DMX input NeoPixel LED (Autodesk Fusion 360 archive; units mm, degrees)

design "DMX input NeoPixel LED" references "3-D NC5FAH", "3D File NC5MAH", "nac3mpxxa", "ELR-02V", "ELR-03V", "5V2AACDC", "xiaodmx"
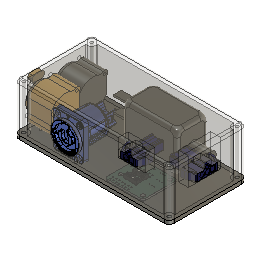
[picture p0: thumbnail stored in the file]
sketch "Sketch1" plane through (0, 0, 0) normal (0, 0, 1) x axis (1, 0, 0)
  line L1 (130, 0) -> (0, 0)
  line L2 (130, 65) -> (130, 0)
  line L3 (0, 65) -> (130, 65)
  line L4 (0, 0) -> (0, 65)
  point P1 (0, 0)
  point P2 (0, 0)
  point P5 (0, 65)
  point P3 (130, 0)
  horizontal L1
  vertical L2
  horizontal L3
  vertical L4
  coincident P1 P2
  dimension "d1" distance P2 P5 = 65
  dimension "d2" distance P2 P3 = 130
component_insert "Component Insert1"
component_insert "Component Insert2"
component_insert "Component Insert3"
component_insert "Component Insert4"
component_insert "Component Insert5"
position "Position1"
extrude "Extrude1" new body sketch "Sketch1" along normal blind 40
fillet "Fillet1" radius 4
shell "Shell1" innerThickness 3
position "Position2"
sketch "Sketch2" plane through (0, 0, 0) normal (0, 0, -1) x axis (1, 0, 0)
  line L1 (126, -3) -> (4, -3)
  line L2 (127, -61) -> (127, -4)
  line L3 (4, -62) -> (126, -62)
  line L4 (3, -4) -> (3, -61)
  line L5 (126, -65) -> (4, -65)
  line L6 (130, -4) -> (130, -61)
  line L7 (4, 0) -> (126, 0)
  line L8 (0, -61) -> (0, -4)
  arc A1 centre (4, -4) radius 1 clockwise from (3, -4) to (4, -3)
  arc A2 centre (126, -4) radius 1 clockwise from (126, -3) to (127, -4)
  arc A3 centre (126, -61) radius 1 clockwise from (127, -61) to (126, -62)
  arc A4 centre (4, -61) radius 1 clockwise from (4, -62) to (3, -61)
  arc A5 centre (4, -61) radius 4 clockwise from (4, -65) to (0, -61)
  arc A6 centre (126, -61) radius 4 clockwise from (130, -61) to (126, -65)
  arc A7 centre (126, -4) radius 4 clockwise from (126, 0) to (130, -4)
  arc A8 centre (4, -4) radius 4 clockwise from (0, -4) to (4, 0)
  circle C1 centre (4, -61) radius 4
  circle C2 centre (4, -4) radius 4
  circle C3 centre (126, -4) radius 4
  circle C4 centre (126, -61) radius 4
  circle C5 centre (4, -4) radius 1.2
  circle C6 centre (126, -4) radius 1.2
  circle C7 centre (126, -61) radius 1.2
  circle C8 centre (4, -61) radius 1.2
  concentric A4 C1
  concentric A1 C2
  concentric A2 C3
  concentric A3 C4
  concentric A1 C5
  concentric A2 C6
  concentric A3 C7
  concentric C1 C8
  dimension "d13" diameter C5 = 2.4
  dimension "d14" diameter C6 = 2.4
  dimension "d15" diameter C7 = 2.4
  dimension "d16" diameter C8 = 2.4
position "Position3"
extrude "Extrude2" add sketch "Sketch2" profile of A1 L1 A2 L2 A3 L3 A4 L4 C1 C2 C3 C4 against normal blind 40
extrude "Extrude3" cut sketch "Sketch2" profile of A1 L1 A2 L2 A3 L3 A4 L4 C5 C6 C7 C8 against normal blind 37
sketch "Sketch3" plane through (0, 0, 0) normal (0, 0, -1) x axis (1, 0, 0)
  line L1 (126, -65) -> (4, -65)
  line L2 (130, -4) -> (130, -61)
  line L3 (4, 0) -> (126, 0)
  line L4 (0, -61) -> (0, -4)
  line L5 (122.127, -3) -> (7.873, -3)
  line L6 (127, -57.127) -> (127, -7.873)
  line L7 (7.873, -62) -> (122.127, -62)
  line L8 (3, -7.873) -> (3, -57.127)
  arc A1 centre (4, -61) radius 4 clockwise from (4, -65) to (0, -61)
  arc A2 centre (126, -61) radius 4 clockwise from (130, -61) to (126, -65)
  arc A3 centre (126, -4) radius 4 clockwise from (126, 0) to (130, -4)
  arc A4 centre (4, -4) radius 4 clockwise from (0, -4) to (4, 0)
  arc A5 centre (126, -4) radius 4 clockwise from (127, -7.873) to (122.127, -3)
  arc A6 centre (126, -61) radius 4 clockwise from (122.127, -62) to (127, -57.127)
  arc A7 centre (4, -61) radius 4 clockwise from (3, -57.127) to (7.873, -62)
  arc A8 centre (4, -4) radius 4 clockwise from (7.873, -3) to (3, -7.873)
  circle C1 centre (4, -61) radius 1.2
  circle C2 centre (4, -4) radius 1.2
  circle C3 centre (126, -61) radius 1.2
  circle C4 centre (126, -4) radius 1.2
extrude "Extrude4" new body sketch "Sketch3" along normal blind 3
sketch "Sketch4" plane through (0, 0, 1.56) normal (0, 0, 1) x axis (-1, 0, 0)
  line L1 (-74.3328, -3.6506) -> (-74.1899, -3.6531)
  line L2 (-102.3114, -3.6506) -> (-74.3328, -3.6506)
  line L3 (-102.4543, -3.6531) -> (-102.3114, -3.6506)
  line L4 (-104.3114, -5.6506) -> (-104.3089, -5.5077)
  line L5 (-104.3114, -30.6828) -> (-104.3114, -5.6506)
  line L6 (-104.3089, -30.8257) -> (-104.3114, -30.6828)
  line L7 (-102.3114, -32.6828) -> (-102.4543, -32.6803)
  line L8 (-74.3328, -32.6828) -> (-102.3114, -32.6828)
  line L9 (-74.1899, -32.6803) -> (-74.3328, -32.6828)
  line L10 (-72.3328, -30.6828) -> (-72.3353, -30.8257)
  line L11 (-72.3328, -5.6506) -> (-72.3328, -30.6828)
  line L12 (-72.3353, -5.5077) -> (-72.3328, -5.6506)
  arc A1 centre (-74.3328, -5.6506) radius 2.0026 clockwise from (-74.1899, -3.6531) to (-72.3353, -5.5077)
  arc A2 centre (-102.3114, -5.6506) radius 2.0026 clockwise from (-104.3089, -5.5077) to (-102.4543, -3.6531)
  arc A3 centre (-102.3114, -30.6828) radius 2.0026 clockwise from (-102.4543, -32.6803) to (-104.3089, -30.8257)
  arc A4 centre (-74.3328, -30.6828) radius 2.0026 clockwise from (-72.3353, -30.8257) to (-74.1899, -32.6803)
  circle C1 centre (-101.238, -6.724) radius 1.5875
  circle C2 centre (-101.238, -29.584) radius 1.5875
  circle C3 centre (-99.65, -17.942) radius 0.3374
  circle C4 centre (-99.65, -24.25) radius 0.3374
  circle C5 centre (-97.65, -17.942) radius 0.3374
  circle C6 centre (-97.65, -24.25) radius 0.3374
  circle C7 centre (-96.094, -30.6) radius 0.3374
  circle C8 centre (-95.65, -17.942) radius 0.3374
  circle C9 centre (-95.65, -24.25) radius 0.3374
  circle C10 centre (-94.094, -30.6) radius 0.3374
  circle C11 centre (-92.094, -30.6) radius 0.3374
  circle C12 centre (-90.57, -5.2) radius 0.4874
  circle C13 centre (-90.57, -7.74) radius 0.4874
  circle C14 centre (-90.57, -22.98) radius 0.4874
  circle C15 centre (-90.57, -25.52) radius 0.4874
  circle C16 centre (-90.58, -11.56) radius 0.3874
  circle C17 centre (-90.58, -19.18) radius 0.3874
  circle C18 centre (-88.03, -5.2) radius 0.4874
  circle C19 centre (-88.03, -7.74) radius 0.4874
  circle C20 centre (-88.03, -22.98) radius 0.4874
  circle C21 centre (-88.03, -25.52) radius 0.4874
  circle C22 centre (-88.04, -11.56) radius 0.3874
  circle C23 centre (-88.04, -19.18) radius 0.3874
  circle C24 centre (-87.268, -30.6) radius 0.4874
  circle C25 centre (-85.49, -5.2) radius 0.4874
  circle C26 centre (-85.49, -7.74) radius 0.4874
  circle C27 centre (-85.49, -22.98) radius 0.4874
  circle C28 centre (-85.49, -25.52) radius 0.4874
  circle C29 centre (-85.5, -11.56) radius 0.3874
  circle C30 centre (-85.5, -19.18) radius 0.3874
  circle C31 centre (-84.728, -30.6) radius 0.4874
  circle C32 centre (-82.95, -5.2) radius 0.4874
  circle C33 centre (-82.95, -7.74) radius 0.4874
  circle C34 centre (-82.95, -22.98) radius 0.4874
  circle C35 centre (-82.95, -25.52) radius 0.4874
  circle C36 centre (-82.96, -11.56) radius 0.3874
  circle C37 centre (-82.96, -19.18) radius 0.3874
  circle C38 centre (-80.434, -28.06) radius 0.4874
  circle C39 centre (-80.434, -30.6) radius 0.4874
  circle C40 centre (-80.41, -5.2) radius 0.4874
  circle C41 centre (-80.41, -7.74) radius 0.4874
  circle C42 centre (-80.41, -22.98) radius 0.4874
  circle C43 centre (-80.41, -25.52) radius 0.4874
  circle C44 centre (-77.894, -28.06) radius 0.4874
  circle C45 centre (-77.894, -30.6) radius 0.4874
  circle C46 centre (-77.87, -5.2) radius 0.4874
  circle C47 centre (-77.87, -7.74) radius 0.4874
  circle C48 centre (-77.87, -22.98) radius 0.4874
  circle C49 centre (-77.87, -25.52) radius 0.4874
  circle C50 centre (-76.6, -12.82) radius 1.5875
  circle C51 centre (-75.354, -28.06) radius 0.4874
  circle C52 centre (-75.354, -30.6) radius 0.4874
  circle C53 centre (-75.33, -5.2) radius 0.4874
  circle C54 centre (-75.33, -7.74) radius 0.4874
  circle C55 centre (-75.33, -22.98) radius 0.4874
  circle C56 centre (-75.33, -25.52) radius 0.4874
extrude "Extrude5" cut sketch "Sketch4" profile of C1 C2 C50 against normal blind 20
sketch "Sketch5" plane through (0, 0, 0) normal (0, 0, 1) x axis (-1, 0, 0)
  line L1 (0, -4) -> (0, -61)
  line L2 (-126, 0) -> (-4, 0)
  line L3 (-130, -61) -> (-130, -4)
  line L4 (-4, -65) -> (-126, -65)
  arc A1 centre (-4, -4) radius 4 clockwise from (-4, 0) to (0, -4)
  arc A2 centre (-126, -4) radius 4 clockwise from (-130, -4) to (-126, 0)
  arc A3 centre (-126, -61) radius 4 clockwise from (-126, -65) to (-130, -61)
  arc A4 centre (-4, -61) radius 4 clockwise from (0, -61) to (-4, -65)
  circle C1 centre (-4, -61) radius 1.2
  circle C2 centre (-126, -61) radius 1.2
  circle C3 centre (-126, -4) radius 1.2
  circle C4 centre (-4, -4) radius 1.2
  circle C5 centre (-101.238, -6.724) radius 1.5875
  circle C6 centre (-76.6, -12.82) radius 1.5875
  circle C7 centre (-101.238, -29.584) radius 1.5875
  circle C8 centre (-4, -4) radius 1.5
  circle C9 centre (-4, -61) radius 1.5
  circle C10 centre (-126, -61) radius 1.5
  circle C11 centre (-126, -4) radius 1.5
  concentric A1 C8
  concentric A4 C9
  concentric A3 C10
  concentric A2 C11
  dimension "d23" diameter C8 = 3
  dimension "d24" diameter C9 = 3
  dimension "d25" diameter C10 = 3
  dimension "d26" diameter C11 = 3
extrude "Extrude6" cut sketch "Sketch5" profile of C1 C2 C3 C4 C8 C9 C10 C11 against normal blind 10
sketch "Sketch6" plane through (0, 0, 0) normal (-1, 0, 0) x axis (0, -1, 0)
  line L1 (-61, 0) -> (-61, 40)
  line L2 (-4, 0) -> (-61, 0)
  line L3 (-4, 40) -> (-4, 0)
  line L4 (-61, 40) -> (-4, 40)
step "GeometricRelationship4" Offset 0
step "GeometricRelationship5" Offset 0
position "Position4"
sketch "Sketch8" plane through (0, 0, 0) normal (-1, 0, 0) x axis (0, -1, 0)
  line L1 (-61, 0) -> (-61, 40)
  line L2 (-4, 0) -> (-61, 0)
  line L3 (-4, 40) -> (-4, 0)
  line L4 (-61, 40) -> (-4, 40)
  line L5 (-4, 0) -> (-61, 40)
  line L6 (-61, 0) -> (-4, 40)
  line L7 (-4, 17) -> (-61, 17)
  line L8 (-32.5, 0) -> (-32.5, 40)
  line L9 (-4, 17) -> (-32.5, 17)
  arc A1 centre (-20.6497, 16.4734) radius 11 clockwise from (-18.1497, 27.1856) to (-23.1497, 27.1856)
  arc A2 centre (-44.2658, 16.4734) radius 8.25 clockwise from (-37.7957, 21.592) to (-39.1472, 22.9435)
  circle C1 centre (-20.5, 17) radius 11
  circle C2 centre (-44.5, 17) radius 11
  circle C3 centre (-30.4, 26.9) radius 1.5
  circle C4 centre (-10.6, 7.1) radius 1.5
  circle C5 centre (-34.6, 7.1) radius 1.5
  circle C6 centre (-54.4, 26.9) radius 1.5
  point P2 (-61, 40)
  point P12 (-61, 40)
  point P4 (-4, 0)
  point P13 (-4, 0)
  point P5 (-4, 40)
  point P14 (-4, 40)
  point P3 (-61, 0)
  point P15 (-61, 0)
  point P16 (-61, 17)
  point P17 (-4, 17)
  point P18 (-32.5, 20)
  point P19 (-32.5, 40)
  point P20 (-32.5, 0)
  point P21 (-32.5, 17)
  point P22 (-32.5, 17)
  point P23 (-20.5, 17)
  point P24 (-44.5, 17)
  point P25 (-30.4, 26.9)
  point P26 (-10.6, 7.1)
  point P27 (-34.6, 7.1)
  point P28 (-54.4, 26.9)
  coincident P2 P12
  coincident P4 P13
  coincident P5 P14
  coincident P3 P15
  coincident L1 P16
  coincident L3 P17
  perpendicular L3 L7
  midpoint L6 P18
  midpoint L4 P19
  midpoint L2 P20
  midpoint L7 P21
  coincident P21 P22
  coincident L9 P23
  coincident L7 P24
  dimension "d79" distance L7 P18 = 3
  dimension "d80" diameter C1 = 22
  dimension "d81" diameter C2 = 22
  dimension "d82" distance P23 P24 = 24
  dimension "d83" distance P21 P23 = 12
  dimension "d84" diameter C3 = 3
  dimension "d85" distance P23 P25 = 9.9
  dimension "d86" distance L9 P25 = 9.9
  dimension "d87" diameter C4 = 3
  dimension "d88" distance P23 P26 = 9.9
  dimension "d89" distance L9 P26 = 9.9
  dimension "d90" diameter C5 = 3
  dimension "d91" distance L7 P27 = 9.9
  dimension "d92" distance P24 P27 = 9.9
  dimension "d93" diameter C6 = 3
  dimension "d94" distance P24 P28 = 9.9
  dimension "d95" distance L7 P28 = 9.9
extrude "Extrude7" cut sketch "Sketch8" profile of C1 C2 C3 C4 C5 C6 against normal blind 9.68
sketch "Sketch9" plane through (0, 0, 0) normal (0, -1, 0) x axis (1, 0, 0)
  line L1 (126, 40) -> (126, 0)
  line L2 (4, 40) -> (126, 40)
  line L3 (4, 0) -> (4, 40)
  line L4 (126, 0) -> (4, 0)
  line L5 (126, 0) -> (4, 40)
  line L6 (4, 0) -> (126, 40)
  line L7 (4, 20) -> (126, 20)
  line L8 (4, 17) -> (126, 17)
  line L9 (65, 0) -> (65, 40)
  line L10 (65, 10.3719) -> (4, 10.3719)
  line L11 (34.5, 40) -> (34.5, 10.3719)
  line L12 (65, 14.0399) -> (34.5, 14.0399)
  line L13 (49.75, 40) -> (49.75, 14.0399)
  line L14 (65, 17) -> (126, 17)
  line L15 (95.5, 40) -> (95.5, 17)
  line L16 (84.25, 34.5) -> (106.75, 34.5)
  line L17 (84.25, 22.5) -> (84.25, 34.5)
  line L18 (106.75, 22.5) -> (84.25, 22.5)
  line L19 (106.75, 34.5) -> (106.75, 22.5)
  line L20 (84.25, 22.5) -> (106.75, 34.5)
  line L21 (106.75, 22.5) -> (84.25, 34.5)
  line L22 (84.25, 40) -> (84.25, 34.5)
  line L23 (106.75, 40) -> (106.75, 34.5)
  line L24 (87.25, 31.5) -> (103.75, 31.5)
  line L25 (87.25, 25.5) -> (87.25, 31.5)
  line L26 (103.75, 25.5) -> (87.25, 25.5)
  line L27 (103.75, 31.5) -> (103.75, 25.5)
  line L28 (87.25, 25.5) -> (103.75, 31.5)
  line L29 (103.75, 25.5) -> (87.25, 31.5)
  line L30 (92.9, 36.5) -> (98.1, 36.5)
  line L31 (92.9, 31.5) -> (92.9, 36.5)
  line L32 (98.1, 31.5) -> (92.9, 31.5)
  line L33 (98.1, 36.5) -> (98.1, 31.5)
  line L34 (92.9, 31.5) -> (98.1, 36.5)
  line L35 (98.1, 31.5) -> (92.9, 36.5)
  line L36 (88, 31.5) -> (103, 31.5)
  line L37 (88, 25.5) -> (88, 31.5)
  line L38 (103, 25.5) -> (88, 25.5)
  line L39 (103, 31.5) -> (103, 25.5)
  line L40 (88, 25.5) -> (103, 31.5)
  line L41 (103, 25.5) -> (88, 31.5)
  line L42 (92.9, 31.5) -> (98.1, 31.5)
  line L43 (92.9, 32.35) -> (92.9, 31.5)
  line L44 (98.1, 32.35) -> (92.9, 32.35)
  line L45 (98.1, 31.5) -> (98.1, 32.35)
  line L46 (92.9, 32.35) -> (98.1, 31.5)
  line L47 (98.1, 32.35) -> (92.9, 31.5)
  line L48 (49.75, 15.3146) -> (34.5, 15.3146)
  line L49 (42.125, 40) -> (42.125, 15.3146)
  circle C1 centre (42.125, 17) radius 12
  circle C2 centre (32.625, 29) radius 1.5
  circle C3 centre (51.625, 5) radius 1.5
  point P4 (4, 40)
  point P6 (4, 40)
  point P2 (126, 0)
  point P7 (126, 0)
  point P3 (126, 40)
  point P8 (126, 40)
  point P5 (4, 0)
  point P9 (4, 0)
  point P10 (126, 20)
  point P11 (4, 20)
  point P12 (126, 17)
  point P13 (4, 17)
  point P14 (65, 40)
  point P15 (65, 0)
  point P16 (4, 10.3719)
  point P17 (65, 10.3719)
  point P18 (34.5, 10.3719)
  point P19 (34.5, 40)
  point P20 (34.5, 14.0399)
  point P21 (65, 14.0399)
  point P22 (49.75, 14.0399)
  point P23 (49.75, 40)
  point P25 (65, 17)
  point P26 (95.5, 17)
  point P27 (95.5, 40)
  point P28 (95.5, 28.5)
  point P33 (95.5, 28.5)
  point P34 (84.25, 40)
  point P35 (106.75, 40)
  point P40 (95.5, 28.5)
  point P45 (95.5, 34)
  point P43 (92.9, 31.5)
  point P50 (95.5, 28.5)
  point P55 (95.5, 31.925)
  point P52 (92.9, 31.5)
  point P56 (32.625, 29)
  point P57 (32.625, 29)
  point P58 (51.625, 5)
  point P59 (51.625, 5)
  point P60 (34.5, 15.3146)
  point P61 (49.75, 15.3146)
  point P62 (42.125, 15.3146)
  point P63 (42.125, 40)
  point P64 (42.125, 17)
  point P31 (84.25, 22.5)
  point P32 (106.75, 22.5)
  point P30 (84.25, 34.5)
  point P38 (87.25, 25.5)
  point P39 (103.75, 25.5)
  point P37 (87.25, 31.5)
  point P44 (98.1, 31.5)
  point P42 (92.9, 36.5)
  point P48 (88, 25.5)
  point P49 (103, 25.5)
  point P47 (88, 31.5)
  point P53 (92.9, 32.35)
  coincident P4 P6
  coincident P2 P7
  coincident P3 P8
  coincident P5 P9
  midpoint L1 P10
  midpoint L3 P11
  coincident L1 P12
  coincident L3 P13
  perpendicular L3 L8
  midpoint L2 P14
  midpoint L4 P15
  coincident L3 P16
  coincident L9 P17
  perpendicular L9 L10
  midpoint L10 P18
  coincident L2 P19
  perpendicular L2 L11
  coincident L11 P20
  coincident L9 P21
  perpendicular L9 L12
  midpoint L12 P22
  coincident L2 P23
  perpendicular L2 L13
  midpoint L8 P25
  midpoint L14 P26
  coincident L2 P27
  perpendicular L2 L15
  midpoint L15 P28
  horizontal L16
  perpendicular L16 L17
  parallel L16 L18
  parallel L17 L19
  coincident L20 P33
  coincident L21 P33
  coincident P28 P33
  coincident L2 P34
  perpendicular L2 L22
  coincident L2 P35
  perpendicular L2 L23
  horizontal L24
  perpendicular L24 L25
  parallel L24 L26
  parallel L25 L27
  coincident L28 P40
  coincident L29 P40
  coincident P28 P40
  horizontal L30
  perpendicular L30 L31
  parallel L30 L32
  parallel L31 L33
  coincident L34 P45
  coincident L35 P45
  coincident L15 P45
  coincident L24 P43
  horizontal L36
  perpendicular L36 L37
  parallel L36 L38
  parallel L37 L39
  coincident L40 P50
  coincident L41 P50
  coincident P33 P50
  horizontal L42
  perpendicular L42 L43
  parallel L42 L44
  parallel L43 L45
  coincident L46 P55
  coincident L47 P55
  coincident L15 P55
  coincident P43 P52
  coincident P56 P57
  coincident P58 P59
  coincident L11 P60
  coincident L13 P61
  perpendicular L13 L48
  midpoint L48 P62
  coincident L2 P63
  perpendicular L2 L49
  coincident L49 P64
  coincident L8 P64
  dimension "d54" distance L7 L8 = 3
  dimension "d55" diameter C1 = 24
  dimension "d56" distance P31 P32 = 22.5
  dimension "d57" distance P30 P31 = 12
  dimension "d58" distance P38 P39 = 16.5
  dimension "d59" distance P37 P38 = 6
  dimension "d60" distance P43 P44 = 5.2
  dimension "d61" distance P42 P43 = 5
  dimension "d66" distance P48 P49 = 15
  dimension "d67" distance P47 P48 = 6
  dimension "d68" distance P52 P53 = 0.85
  dimension "d72" distance L8 P56 = 12
  dimension "d73" diameter C2 = 3
  dimension "d75" distance L8 P58 = 12
  dimension "d76" diameter C3 = 3
sketch "Sketch10" plane through (130, 0, 0) normal (1, 0, 0) x axis (0, 1, 0)
  line L1 (61, 40) -> (61, 0)
  line L2 (4, 40) -> (61, 40)
  line L3 (4, 0) -> (4, 40)
  line L4 (61, 0) -> (4, 0)
  line L5 (4, 0) -> (61, 40)
  line L6 (61, 0) -> (4, 40)
  line L7 (46, 26) -> (19, 26)
  line L8 (46, 14) -> (46, 26)
  line L9 (19, 14) -> (46, 14)
  line L10 (19, 26) -> (19, 14)
  line L11 (46, 14) -> (19, 26)
  line L12 (19, 14) -> (46, 26)
  line L13 (19, 14) -> (46, 14)
  line L14 (19, 30) -> (19, 14)
  line L15 (46, 30) -> (19, 30)
  line L16 (46, 14) -> (46, 30)
  line L17 (46, 40) -> (46, 30)
  line L18 (19, 40) -> (19, 26)
  point P3 (61, 40)
  point P6 (61, 40)
  point P5 (4, 0)
  point P7 (4, 0)
  point P4 (4, 40)
  point P8 (4, 40)
  point P2 (61, 0)
  point P9 (61, 0)
  point P10 (32.5, 20)
  point P15 (32.5, 20)
  point P19 (46, 40)
  point P20 (19, 40)
  point P13 (46, 14)
  point P14 (19, 14)
  point P12 (46, 26)
  coincident P3 P6
  coincident P5 P7
  coincident P4 P8
  coincident P2 P9
  midpoint L6 P10
  horizontal L7
  perpendicular L7 L8
  parallel L7 L9
  parallel L8 L10
  coincident L11 P15
  coincident L12 P15
  coincident P10 P15
  horizontal L13
  vertical L14
  horizontal L15
  vertical L16
  coincident L2 P19
  perpendicular L2 L17
  coincident L2 P20
  perpendicular L2 L18
  dimension "d38" distance P13 P14 = 27
  dimension "d39" distance P12 P13 = 12
extrude "Extrude9" add sketch "Sketch10" profile of L2 L7 L8 L9 L10 L13 L14 L15 L16 L17 L18 against normal blind 11.2
sketch "Sketch12" plane through (130, 0, 0) normal (1, 0, 0) x axis (0, 1, 0)
  line L1 (22, 23) -> (43, 23)
  line L2 (22, 17) -> (22, 23)
  line L3 (43, 17) -> (22, 17)
  line L4 (43, 23) -> (43, 17)
  line L5 (22, 17) -> (43, 23)
  line L6 (43, 17) -> (22, 23)
  line L7 (32.5, 40) -> (32.5, 0)
  line L8 (29.9, 28) -> (35.1, 28)
  line L9 (29.9, 23) -> (29.9, 28)
  line L10 (35.1, 23) -> (29.9, 23)
  line L11 (35.1, 28) -> (35.1, 23)
  line L12 (29.9, 23) -> (35.1, 28)
  line L13 (35.1, 23) -> (29.9, 28)
  line L14 (22.65, 17) -> (42.35, 17)
  line L15 (22.65, 23) -> (22.65, 17)
  line L16 (42.35, 23) -> (22.65, 23)
  line L17 (42.35, 17) -> (42.35, 23)
  line L18 (22.65, 23) -> (42.35, 17)
  line L19 (42.35, 23) -> (22.65, 17)
  line L20 (29.9, 23.85) -> (35.1, 23.85)
  line L21 (29.9, 23) -> (29.9, 23.85)
  line L22 (35.1, 23) -> (29.9, 23)
  line L23 (35.1, 23.85) -> (35.1, 23)
  line L24 (29.9, 23) -> (35.1, 23.85)
  line L25 (35.1, 23) -> (29.9, 23.85)
  point P6 (32.5, 20)
  point P7 (32.5, 20)
  point P14 (32.5, 25.5)
  point P12 (29.9, 23)
  point P19 (32.5, 20)
  point P24 (32.5, 23.425)
  point P22 (29.9, 23)
  point P4 (22, 17)
  point P5 (43, 17)
  point P3 (22, 23)
  point P13 (35.1, 23)
  point P11 (29.9, 28)
  point P17 (22.65, 23)
  point P18 (42.35, 23)
  point P16 (22.65, 17)
  point P23 (35.1, 23)
  point P21 (29.9, 23.85)
  horizontal L1
  perpendicular L1 L2
  parallel L1 L3
  parallel L2 L4
  coincident L5 P6
  coincident L6 P6
  coincident P6 P7
  parallel L4 L7
  horizontal L8
  perpendicular L8 L9
  parallel L8 L10
  parallel L9 L11
  coincident L12 P14
  coincident L13 P14
  coincident L7 P14
  coincident L1 P12
  horizontal L14
  perpendicular L14 L15
  parallel L14 L16
  parallel L15 L17
  coincident L18 P19
  coincident L19 P19
  coincident P6 P19
  horizontal L20
  perpendicular L20 L21
  parallel L20 L22
  parallel L21 L23
  coincident L24 P24
  coincident L25 P24
  coincident L7 P24
  coincident P12 P22
  dimension "d42" distance P4 P5 = 21
  dimension "d43" distance P3 P4 = 6
  dimension "d44" distance P12 P13 = 5.2
  dimension "d45" distance P11 P12 = 5
  dimension "d48" distance P17 P18 = 19.7
  dimension "d49" distance P16 P17 = 6
  dimension "d50" distance P22 P23 = 5.2
  dimension "d51" distance P21 P22 = 0.85
extrude "Extrude10" cut sketch "Sketch12" profile of L1 L2 L3 L4 L8 L9 L10 L11 against normal blind 9.2
extrude "Extrude11" cut sketch "Sketch12" profile of L1 L3 L9 L10 L11 L14 L15 L16 L17 L20 L21 L22 L23 against normal blind 12
position "Position7"
extrude "Extrude12" add sketch "Sketch9" profile of L2 L16 L17 L18 L19 L22 L23 L24 L25 L26 L27 L30 L31 L32 L33 L36 L37 L38 L39 L42 L43 L44 L45 against normal blind 11.2
extrude "Extrude13" cut sketch "Sketch9" profile of L16 L24 L25 L26 L27 L30 L31 L32 L33 L36 L37 L38 L39 L42 L43 L44 L45 against normal blind 9.2
extrude "Extrude14" cut sketch "Sketch9" profile of L24 L26 L31 L32 L33 L36 L37 L38 L39 L42 L43 L44 L45 against normal blind 20
extrude "Extrude15" cut sketch "Sketch9" profile of C1 C2 C3 against normal blind 10
fillet "Fillet2" radius 3
component_insert "Component Insert6"
component_insert "Component Insert7"
step "GeometricRelationship6" Offset 0
step "GeometricRelationship8" Angle 0

design "5V2AACDC"
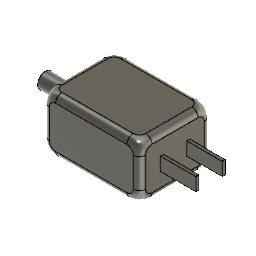
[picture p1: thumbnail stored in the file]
sketch "Sketch1" plane through (0, 0, 0) normal (0, 0, 1) x axis (1, 0, 0)
  line L1 (-23, 17) -> (23, 17)
  line L2 (-23, -17) -> (-23, 17)
  line L3 (23, -17) -> (-23, -17)
  line L4 (23, 17) -> (23, -17)
  line L5 (-23, -17) -> (23, 17)
  line L6 (23, -17) -> (-23, 17)
  point P6 (0, 0)
  point P1 (0, 0)
  point P4 (-23, -17)
  point P5 (23, -17)
  point P3 (-23, 17)
  horizontal L1
  perpendicular L1 L2
  parallel L1 L3
  parallel L2 L4
  coincident L5 P6
  coincident L6 P6
  coincident P1 P6
  dimension "d3" distance P4 P5 = 46
  dimension "d4" distance P3 P4 = 34
extrude "Extrude1" new body sketch "Sketch1" profile of L1 L2 L3 L4 along normal blind 26
sketch "Sketch2" plane through (-23, 0, 0) normal (-1, 0, 0) x axis (0, -1, 0)
  line L1 (17, 0) -> (-17, 0)
  line L2 (17, 26) -> (17, 0)
  line L3 (-17, 26) -> (17, 26)
  line L4 (-17, 0) -> (-17, 26)
  circle C1 centre (0, 13) radius 3.75
  dimension "d5" diameter C1 = 7.5
extrude "Extrude2" add sketch "Sketch2" profile of C1 along normal blind 16
sketch "Sketch3" plane through (23, 0, 0) normal (1, 0, 0) x axis (0, 1, 0)
  line L1 (17, 0) -> (-17, 0)
  line L2 (17, 26) -> (17, 0)
  line L3 (-17, 26) -> (17, 26)
  line L4 (-17, 0) -> (-17, 26)
  line L5 (-7.05, 16.175) -> (7.05, 16.175)
  line L6 (-7.05, 9.825) -> (-7.05, 16.175)
  line L7 (7.05, 9.825) -> (-7.05, 9.825)
  line L8 (7.05, 16.175) -> (7.05, 9.825)
  line L9 (-7.05, 9.825) -> (7.05, 16.175)
  line L10 (7.05, 9.825) -> (-7.05, 16.175)
  line L11 (-5.55, 16.175) -> (-7.05, 16.175)
  line L12 (-5.55, 9.825) -> (-5.55, 16.175)
  line L13 (-7.05, 9.825) -> (-5.55, 9.825)
  line L14 (-7.05, 16.175) -> (-7.05, 9.825)
  line L15 (5.55, 16.175) -> (7.05, 16.175)
  line L16 (5.55, 9.825) -> (5.55, 16.175)
  line L17 (7.05, 9.825) -> (5.55, 9.825)
  line L18 (7.05, 16.175) -> (7.05, 9.825)
  point P10 (0, 13)
  point P8 (-7.05, 9.825)
  point P9 (7.05, 9.825)
  point P7 (-7.05, 16.175)
  point P11 (-5.55, 16.175)
  point P6 (7.05, 16.175)
  point P14 (5.55, 16.175)
  horizontal L5
  perpendicular L5 L6
  parallel L5 L7
  parallel L6 L8
  coincident L9 P10
  coincident L10 P10
  horizontal L11
  vertical L12
  horizontal L13
  vertical L14
  horizontal L15
  vertical L16
  horizontal L17
  vertical L18
  dimension "d8" distance P8 P9 = 14.1
  dimension "d9" distance P7 P8 = 6.35
  dimension "d10" distance P7 P11 = 1.5
  dimension "d11" distance P6 P14 = 1.5
extrude "Extrude3" add sketch "Sketch3" profile of L11 L12 L13 L14 L15 L16 L17 L18 along normal blind 17
fillet "Fillet1" radius 3

design "3-D NC5FAH"
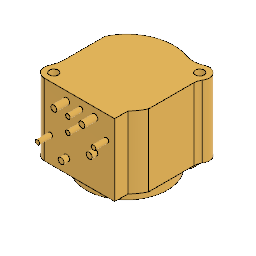
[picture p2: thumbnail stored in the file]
description: Part Number
part number: D-NC5FAH
base_feature "Base Feature"

design "ELR-02V"
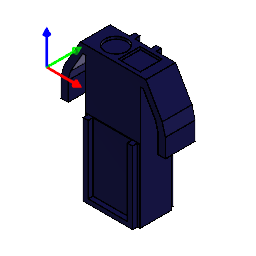
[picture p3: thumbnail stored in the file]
description: STEP AP214
part number: ELR-02V
base_feature "Base Feature"
step "CoordinateSystem" OffsetX 0 OffsetY 0 OffsetZ 0 AngleX 0 AngleY 0 AngleZ 0

design "ELR-03V"
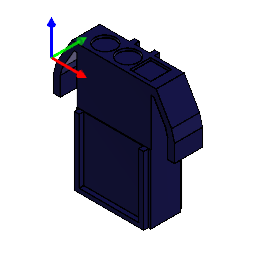
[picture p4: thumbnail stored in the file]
description: STEP AP214
part number: ELR-03V
base_feature "Base Feature"
step "CoordinateSystem" OffsetX 0 OffsetY 0 OffsetZ 0 AngleX 0 AngleY 0 AngleZ 0

design "nac3mpxxa"
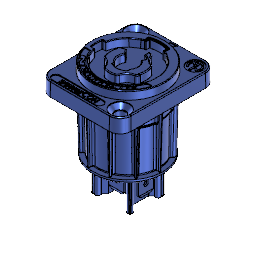
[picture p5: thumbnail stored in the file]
description: Part Number
part number: NAC3MPXXA
base_feature "Base Feature"

design "3D File NC5MAH"
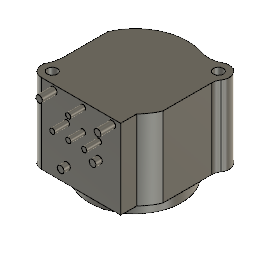
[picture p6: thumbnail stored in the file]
description: Part Number
part number: D-NC5MAH
base_feature "Base Feature"

design "xiaodmx"
description: KiCad electronic assembly
part number: xiaodmx 1
description: Part Number
part number: xiaodmx 1.2.1
part number: xiaodmx 1.2.2
part number: PinHeader-01x07_P2.54mm_Vertical_THT
part number: xiaodmx 1.5.1
part number: xiaodmx 1.5.2
part number: PinHeader-01x02_P2.54mm_Vertical_THT
part number: xiaodmx 1.6.1
part number: xiaodmx 1.6.2
part number: xiaodmx 1.6.3
base_feature "Base Feature1"
base_feature "Base Feature1"
base_feature "Base Feature1"
base_feature "Base Feature1"
base_feature "Base Feature1"
base_feature "Base Feature1"
base_feature "Base Feature1"
base_feature "Base Feature1"
base_feature "Base Feature1"
base_feature "Base Feature1"
base_feature "Base Feature1"
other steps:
create_component "CreateComponent1"
create_component "CreateComponent2"
create_component "CreateComponent1"
create_component "CreateComponent2"
create_component "CreateComponent3"
create_component "CreateComponent1"
create_component "CreateComponent2"
create_component "CreateComponent4"
create_component "CreateComponent1"
create_component "CreateComponent2"
create_component "CreateComponent3"
create_component "CreateComponent5"
create_component "CreateComponent6"
create_component "CreateComponent7"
